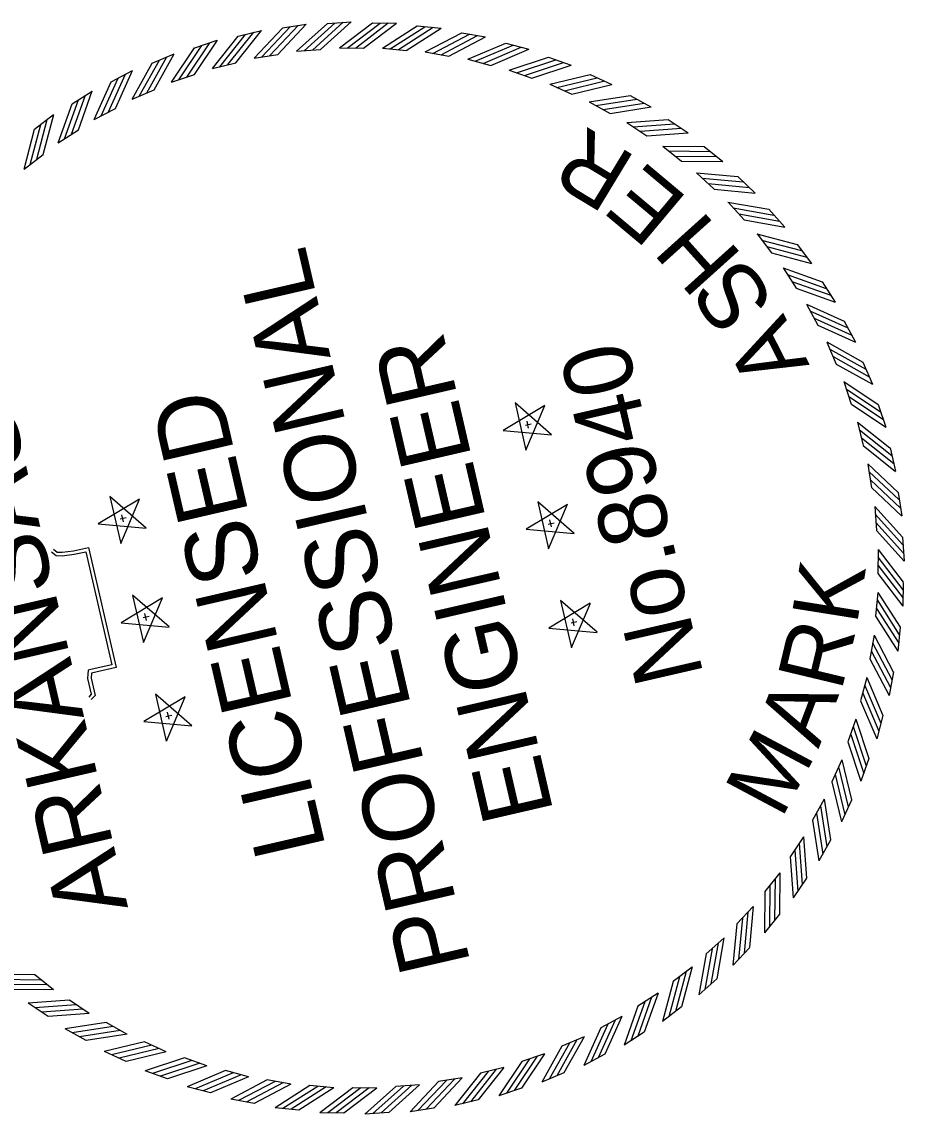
# Model space of a CAD drawing. Extents: x 634644 to 1109508, y 286699 to 700437.
# Drawn here: x 1109100 to 1109183.5, y 700245.2 to 700348.6 of the extents above; entities that cross this region are included whole.
import ezdxf

# ---------------------------------------------------------------- set-up
doc = ezdxf.new("R2010")
doc.units = 0
doc.layers.add('R_Border', color=7, linetype='Continuous')

msp = doc.modelspace()

# ---------------------------------------------------------------- linework, layer by layer
at = {"layer": 'R_Border'}
for p, q in [((1109120.51, 700347.23), (1109122.71, 700347.76)), ((1109124.71, 700348), (1109126.94, 700348.34)), ((1109128.95, 700348.41), (1109131.21, 700348.57)), ((1109133.21, 700348.48), (1109135.48, 700348.45)), ((1109137.47, 700348.19), (1109139.72, 700347.98)), ((1109116.4, 700346.12), (1109118.54, 700346.83)), ((1109141.68, 700347.55), (1109143.91, 700347.15)), ((1109126.04, 700345.79), (1109128.3, 700345.95)), ((1109130.1, 700346.11), (1109132.37, 700346.08)), ((1109134.17, 700346.09), (1109136.43, 700345.87)), ((1109138.22, 700345.73), (1109140.45, 700345.33)), ((1109145.83, 700346.57), (1109148.02, 700345.99)), ((1109112.38, 700344.68), (1109114.47, 700345.56)), ((1109118.07, 700344.17), (1109120.28, 700344.7)), ((1109122.02, 700345.15), (1109124.27, 700345.49)), ((1109142.23, 700345.03), (1109144.42, 700344.45)), ((1109149.89, 700345.24), (1109152.02, 700344.48)), ((1109108.51, 700342.91), (1109110.51, 700343.96)), ((1109114.22, 700342.87), (1109116.37, 700343.58)), ((1109146.17, 700344.01), (1109148.31, 700343.25)), ((1109153.82, 700343.59), (1109155.88, 700342.66)), ((1109150.01, 700342.67), (1109152.08, 700341.74)), ((1109104.79, 700340.82), (1109106.7, 700342.03)), ((1109110.48, 700341.26), (1109112.57, 700342.14)), ((1109157.6, 700341.62), (1109159.57, 700340.52)), ((1109153.73, 700341.02), (1109155.71, 700339.91)), ((1109101.25, 700338.43), (1109103.05, 700339.8)), ((1109106.89, 700339.34), (1109108.9, 700340.39)), ((1109157.3, 700339.06), (1109159.18, 700337.8)), ((1109161.2, 700339.34), (1109163.08, 700338.08)), ((1109103.48, 700337.13), (1109105.39, 700338.35)), ((1109160.69, 700336.82), (1109162.46, 700335.4)), ((1109164.6, 700336.77), (1109166.37, 700335.36)), ((1109100.25, 700334.65), (1109102.06, 700336.02)), ((1109163.89, 700334.3), (1109165.54, 700332.74)), ((1109167.78, 700333.93), (1109169.43, 700332.38)), ((1109166.87, 700331.53), (1109168.38, 700329.84)), ((1109170.72, 700330.84), (1109172.23, 700329.16)), ((1109169.61, 700328.52), (1109170.98, 700326.71)), ((1109173.39, 700327.51), (1109174.76, 700325.71)), ((1109172.09, 700325.29), (1109173.3, 700323.38)), ((1109175.77, 700323.98), (1109176.99, 700322.07)), ((1109174.29, 700321.87), (1109175.35, 700319.87)), ((1109177.86, 700320.26), (1109178.91, 700318.26)), ((1109176.21, 700318.28), (1109177.1, 700316.2)), ((1109179.63, 700316.38), (1109180.52, 700314.3)), ((1109177.82, 700314.55), (1109178.53, 700312.4)), ((1109149.52, 700312.27), (1109145.6, 700309.92)), ((1109146.71, 700312.52), (1109147.73, 700308.07)), ((1109150.15, 700309.52), (1109146.71, 700312.52)), ((1109147.73, 700308.07), (1109149.52, 700312.27)), ((1109181.08, 700312.37), (1109181.79, 700310.22)), ((1109147.69, 700310.41), (1109148.25, 700310.54)), ((1109148, 700310.14), (1109147.85, 700310.8)), ((1109179.12, 700310.69), (1109179.65, 700308.49)), ((1109145.6, 700309.92), (1109150.15, 700309.52)), ((1109182.19, 700308.26), (1109182.72, 700306.06)), ((1109180.1, 700306.74), (1109180.45, 700304.5)), ((1109111.18, 700303.42), (1109107.27, 700301.07)), ((1109108.38, 700303.67), (1109109.4, 700299.22)), ((1109111.82, 700300.68), (1109108.38, 700303.67)), ((1109109.4, 700299.22), (1109111.19, 700303.42)), ((1109182.95, 700304.06), (1109183.3, 700301.83)), ((1109151.67, 700302.92), (1109147.76, 700300.58)), ((1109148.86, 700303.17), (1109149.89, 700298.72)), ((1109152.31, 700300.18), (1109148.86, 700303.17)), ((1109149.89, 700298.72), (1109151.68, 700302.93)), ((1109180.75, 700302.73), (1109180.91, 700300.46)), ((1109109.36, 700301.56), (1109109.92, 700301.69)), ((1109109.67, 700301.29), (1109109.52, 700301.95)), ((1109150.16, 700300.79), (1109150.01, 700301.46)), ((1109107.27, 700301.07), (1109111.82, 700300.67)), ((1109147.76, 700300.57), (1109152.31, 700300.17)), ((1109149.85, 700301.06), (1109150.41, 700301.19)), ((1109183.37, 700299.82), (1109183.53, 700297.56)), ((1109181.06, 700298.67), (1109181.04, 700296.4)), ((1109183.43, 700295.55), (1109183.41, 700293.29)), ((1109113.34, 700294.07), (1109109.43, 700291.73)), ((1109113.98, 700291.33), (1109110.53, 700294.33)), ((1109110.53, 700294.32), (1109111.56, 700289.87)), ((1109111.56, 700289.87), (1109113.35, 700294.08)), ((1109181.04, 700294.6), (1109180.83, 700292.34)), ((1109153.83, 700293.57), (1109149.92, 700291.23)), ((1109154.47, 700290.83), (1109151.02, 700293.83)), ((1109151.02, 700293.82), (1109152.05, 700289.37)), ((1109152.05, 700289.38), (1109153.84, 700293.58)), ((1109111.52, 700292.21), (1109112.08, 700292.34)), ((1109111.83, 700291.94), (1109111.68, 700292.61)), ((1109152.32, 700291.45), (1109152.17, 700292.11)), ((1109109.43, 700291.72), (1109113.98, 700291.32)), ((1109149.92, 700291.23), (1109154.47, 700290.82)), ((1109152.01, 700291.71), (1109152.57, 700291.84)), ((1109183.14, 700291.3), (1109182.93, 700289.05)), ((1109180.68, 700290.55), (1109180.28, 700288.32)), ((1109182.51, 700287.08), (1109182.11, 700284.86)), ((1109179.99, 700286.54), (1109179.41, 700284.35)), ((1109115.5, 700284.73), (1109111.58, 700282.38)), ((1109116.14, 700281.98), (1109112.69, 700284.98)), ((1109112.69, 700284.97), (1109113.71, 700280.52)), ((1109113.72, 700280.53), (1109115.51, 700284.73)), ((1109113.68, 700282.86), (1109114.24, 700282.99)), ((1109113.99, 700282.6), (1109113.84, 700283.26)), ((1109178.97, 700282.6), (1109178.21, 700280.46)), ((1109181.52, 700282.94), (1109180.94, 700280.75)), ((1109111.59, 700282.38), (1109116.14, 700281.97)), ((1109177.63, 700278.76), (1109176.69, 700276.69)), ((1109180.2, 700278.88), (1109179.44, 700276.75)), ((1109175.97, 700275.04), (1109174.87, 700273.06)), ((1109178.54, 700274.95), (1109177.61, 700272.89)), ((1109174.01, 700271.47), (1109172.75, 700269.59)), ((1109176.57, 700271.17), (1109175.47, 700269.2)), ((1109171.77, 700268.08), (1109170.36, 700266.31)), ((1109174.29, 700267.57), (1109173.03, 700265.69)), ((1109169.25, 700264.88), (1109167.7, 700263.23)), ((1109171.73, 700264.16), (1109170.32, 700262.4)), ((1109166.48, 700261.9), (1109164.79, 700260.39)), ((1109168.89, 700260.98), (1109167.34, 700259.34)), ((1109163.47, 700259.16), (1109161.67, 700257.79)), ((1109103.03, 700257), (1109101.26, 700258.41)), ((1109165.79, 700258.05), (1109164.11, 700256.54)), ((1109102.52, 700254.47), (1109100.64, 700255.73)), ((1109106.43, 700254.75), (1109104.54, 700256.02)), ((1109160.25, 700256.68), (1109158.33, 700255.46)), ((1109162.47, 700255.38), (1109160.67, 700254.01)), ((1109109.99, 700252.8), (1109108.01, 700253.9)), ((1109156.83, 700254.47), (1109154.82, 700253.42)), ((1109106.13, 700252.2), (1109104.15, 700253.3)), ((1109158.94, 700252.99), (1109157.03, 700251.78)), ((1109113.71, 700251.14), (1109111.65, 700252.08)), ((1109153.24, 700252.56), (1109151.15, 700251.67)), ((1109109.91, 700250.22), (1109107.85, 700251.16)), ((1109117.55, 700249.8), (1109115.42, 700250.56)), ((1109149.5, 700250.94), (1109147.35, 700250.23)), ((1109155.22, 700250.91), (1109153.21, 700249.85)), ((1109145.65, 700249.64), (1109143.44, 700249.11)), ((1109113.84, 700248.57), (1109111.71, 700249.33)), ((1109121.49, 700248.78), (1109119.3, 700249.36)), ((1109141.7, 700248.67), (1109139.46, 700248.32)), ((1109151.34, 700249.14), (1109149.26, 700248.25)), ((1109117.89, 700247.25), (1109115.7, 700247.83)), ((1109125.5, 700248.09), (1109123.27, 700248.49)), ((1109129.55, 700247.73), (1109127.3, 700247.94)), ((1109133.62, 700247.71), (1109131.36, 700247.73)), ((1109137.68, 700248.02), (1109135.42, 700247.86)), ((1109147.33, 700247.69), (1109145.18, 700246.98)), ((1109122.04, 700246.26), (1109119.81, 700246.66)), ((1109143.21, 700246.58), (1109141.01, 700246.05)), ((1109126.25, 700245.62), (1109124, 700245.84)), ((1109134.77, 700245.4), (1109132.52, 700245.24)), ((1109139.01, 700245.82), (1109136.78, 700245.47)), ((1109130.51, 700245.34), (1109128.25, 700245.36))]:
    msp.add_line(p, q, dxfattribs=at)
for points in [[(1109120.28, 700344.7), (1109122.71, 700347.76)], [(1109122.02, 700345.14), (1109124.7, 700347.99)], [(1109122.74, 700345.25), (1109125.43, 700348.1)], [(1109123.52, 700345.39), (1109126.2, 700348.24)], [(1109124.26, 700345.49), (1109126.94, 700348.34)], [(1109126.04, 700345.79), (1109128.95, 700348.41)], [(1109126.77, 700345.84), (1109129.67, 700348.46)], [(1109127.55, 700345.91), (1109130.46, 700348.53)], [(1109128.3, 700345.96), (1109131.21, 700348.58)], [(1109130.1, 700346.11), (1109133.21, 700348.48)], [(1109130.82, 700346.09), (1109133.94, 700348.46)], [(1109131.61, 700346.1), (1109134.72, 700348.47)], [(1109132.36, 700346.08), (1109135.48, 700348.45)], [(1109134.17, 700346.08), (1109137.46, 700348.19)], [(1109134.89, 700346.01), (1109138.19, 700348.11)], [(1109135.67, 700345.95), (1109138.97, 700348.06)], [(1109136.42, 700345.87), (1109139.72, 700347.98)], [(1109116.37, 700343.58), (1109118.55, 700346.83)], [(1109118.07, 700344.17), (1109120.51, 700347.23)], [(1109118.78, 700344.33), (1109121.22, 700347.39)], [(1109119.54, 700344.53), (1109121.98, 700347.59)], [(1109138.22, 700345.73), (1109141.68, 700347.55)], [(1109138.93, 700345.59), (1109142.4, 700347.42)], [(1109139.71, 700345.47), (1109143.17, 700347.29)], [(1109140.45, 700345.33), (1109143.91, 700347.15)], [(1109114.22, 700342.87), (1109116.39, 700346.12)], [(1109114.91, 700343.09), (1109117.09, 700346.34)], [(1109115.65, 700343.35), (1109117.83, 700346.6)], [(1109142.23, 700345.03), (1109145.83, 700346.57)], [(1109142.93, 700344.84), (1109146.53, 700346.37)], [(1109143.69, 700344.65), (1109147.29, 700346.19)], [(1109144.42, 700344.45), (1109148.02, 700345.99)], [(1109110.48, 700341.25), (1109112.38, 700344.67)], [(1109111.15, 700341.53), (1109113.06, 700344.95)], [(1109111.87, 700341.85), (1109113.77, 700345.28)], [(1109112.57, 700342.14), (1109114.47, 700345.56)], [(1109146.17, 700344.01), (1109149.88, 700345.24)], [(1109146.85, 700343.76), (1109150.57, 700344.99)], [(1109147.6, 700343.51), (1109151.31, 700344.74)], [(1109108.23, 700340.05), (1109109.84, 700343.62)], [(1109108.9, 700340.39), (1109110.51, 700343.96)], [(1109148.3, 700343.25), (1109152.02, 700344.49)], [(1109150.01, 700342.67), (1109153.81, 700343.59)], [(1109106.89, 700339.34), (1109108.5, 700342.9)], [(1109107.54, 700339.67), (1109109.15, 700343.24)], [(1109150.67, 700342.36), (1109154.47, 700343.28)], [(1109151.39, 700342.06), (1109155.2, 700342.98)], [(1109152.07, 700341.74), (1109155.88, 700342.66)], [(1109104.75, 700337.95), (1109106.06, 700341.64)], [(1109105.39, 700338.35), (1109106.7, 700342.04)], [(1109153.73, 700341.02), (1109157.59, 700341.62)], [(1109103.47, 700337.13), (1109104.79, 700340.82)], [(1109104.09, 700337.51), (1109105.4, 700341.2)], [(1109154.36, 700340.66), (1109158.23, 700341.26)], [(1109155.05, 700340.29), (1109158.92, 700340.89)], [(1109155.71, 700339.92), (1109159.58, 700340.52)], [(1109102.05, 700336.02), (1109103.06, 700339.81)], [(1109100.25, 700334.65), (1109101.25, 700338.43)], [(1109100.83, 700335.08), (1109101.84, 700338.87)], [(1109101.45, 700335.57), (1109102.45, 700339.35)], [(1109157.29, 700339.06), (1109161.2, 700339.34)], [(1109157.89, 700338.65), (1109161.8, 700338.93)], [(1109158.56, 700338.23), (1109162.46, 700338.51)], [(1109159.18, 700337.8), (1109163.08, 700338.08)], [(1109160.69, 700336.82), (1109164.6, 700336.77)], [(1109161.25, 700336.36), (1109165.17, 700336.31)], [(1109161.88, 700335.88), (1109165.79, 700335.84)], [(1109162.46, 700335.4), (1109166.38, 700335.36)], [(1109163.88, 700334.3), (1109167.78, 700333.93)], [(1109164.41, 700333.79), (1109168.31, 700333.43)], [(1109164.99, 700333.27), (1109168.89, 700332.9)], [(1109165.54, 700332.75), (1109169.43, 700332.38)], [(1109166.86, 700331.53), (1109170.72, 700330.84)], [(1109167.34, 700330.98), (1109171.2, 700330.29)], [(1109167.88, 700330.41), (1109171.74, 700329.72)], [(1109168.38, 700329.84), (1109172.23, 700329.16)], [(1109169.6, 700328.52), (1109173.39, 700327.52)], [(1109170.04, 700327.93), (1109173.82, 700326.93)], [(1109170.53, 700327.32), (1109174.31, 700326.32)], [(1109170.98, 700326.71), (1109174.76, 700325.71)], [(1109172.08, 700325.29), (1109175.77, 700323.98)], [(1109172.47, 700324.68), (1109176.16, 700323.36)], [(1109172.91, 700324.02), (1109176.59, 700322.71)], [(1109173.3, 700323.38), (1109176.99, 700322.07)], [(1109174.29, 700321.88), (1109177.86, 700320.26)], [(1109174.62, 700321.23), (1109178.19, 700319.62)], [(1109175, 700320.54), (1109178.57, 700318.93)], [(1109175.35, 700319.87), (1109178.92, 700318.26)], [(1109176.21, 700318.29), (1109179.63, 700316.39)], [(1109176.49, 700317.61), (1109179.91, 700315.71)], [(1109176.81, 700316.9), (1109180.23, 700315)], [(1109177.1, 700316.2), (1109180.52, 700314.3)], [(1109177.82, 700314.55), (1109181.07, 700312.37)], [(1109178.04, 700313.86), (1109181.3, 700311.68)], [(1109178.31, 700313.12), (1109181.56, 700310.94)], [(1109178.54, 700312.4), (1109181.79, 700310.22)], [(1109179.12, 700310.7), (1109182.18, 700308.26)], [(1109179.29, 700309.99), (1109182.35, 700307.55)], [(1109179.49, 700309.23), (1109182.55, 700306.79)], [(1109179.66, 700308.49), (1109182.72, 700306.05)], [(1109180.1, 700306.75), (1109182.95, 700304.06)], [(1109180.2, 700306.03), (1109183.05, 700303.34)], [(1109180.34, 700305.25), (1109183.19, 700302.57)], [(1109180.45, 700304.51), (1109183.3, 700301.82)], [(1109180.75, 700302.73), (1109183.37, 700299.82)], [(1109180.79, 700302), (1109183.41, 700299.09)], [(1109180.86, 700301.22), (1109183.48, 700298.31)], [(1109180.91, 700300.47), (1109183.53, 700297.56)], [(1109102.84, 700298.44), (1109103.28, 700298.09), (1109103.86, 700298.07), (1109104.99, 700298.2), (1109106.09, 700298.45), (1109108.56, 700287.75), (1109106.99, 700287.39), (1109106.33, 700287.23), (1109106.27, 700286.45), (1109106.61, 700284.96), (1109106.37, 700284.7)], [(1109103.04, 700298.7), (1109103.4, 700298.41), (1109103.85, 700298.4), (1109104.93, 700298.53), (1109106.34, 700298.85), (1109108.96, 700287.5), (1109107.06, 700287.06), (1109106.64, 700286.97), (1109106.6, 700286.47), (1109106.98, 700284.86), (1109106.61, 700284.47)], [(1109181.06, 700298.67), (1109183.43, 700295.56)], [(1109181.04, 700297.94), (1109183.41, 700294.83)], [(1109181.05, 700297.16), (1109183.42, 700294.04)], [(1109181.04, 700296.4), (1109183.41, 700293.29)], [(1109181.04, 700294.6), (1109183.14, 700291.3)], [(1109180.91, 700293.09), (1109183.01, 700289.8)], [(1109180.96, 700293.88), (1109183.07, 700290.58)], [(1109180.83, 700292.35), (1109182.93, 700289.05)], [(1109180.54, 700289.83), (1109182.37, 700286.37)], [(1109180.68, 700290.55), (1109182.5, 700287.09)], [(1109180.42, 700289.06), (1109182.25, 700285.6)], [(1109180.28, 700288.32), (1109182.11, 700284.86)], [(1109179.79, 700285.84), (1109181.33, 700282.24)], [(1109179.99, 700286.54), (1109181.52, 700282.94)], [(1109179.61, 700285.07), (1109181.14, 700281.47)], [(1109179.41, 700284.35), (1109180.94, 700280.75)], [(1109178.97, 700282.6), (1109180.2, 700278.89)], [(1109178.72, 700281.92), (1109179.95, 700278.2)], [(1109178.47, 700281.17), (1109179.7, 700277.46)], [(1109178.21, 700280.46), (1109179.44, 700276.75)], [(1109177.63, 700278.76), (1109178.54, 700274.96)], [(1109177.32, 700278.1), (1109178.24, 700274.3)], [(1109176.69, 700276.69), (1109177.61, 700272.89)], [(1109177.01, 700277.38), (1109177.93, 700273.57)], [(1109175.61, 700274.41), (1109176.21, 700270.54)], [(1109175.97, 700275.04), (1109176.57, 700271.18)], [(1109175.24, 700273.72), (1109175.85, 700269.85)], [(1109174.87, 700273.06), (1109175.47, 700269.19)], [(1109174.01, 700271.48), (1109174.29, 700267.57)], [(1109173.18, 700270.21), (1109173.46, 700266.31)], [(1109173.6, 700270.87), (1109173.88, 700266.97)], [(1109172.75, 700269.59), (1109173.04, 700265.69)], [(1109171.31, 700267.52), (1109171.27, 700263.6)], [(1109171.77, 700268.08), (1109171.73, 700264.17)], [(1109170.36, 700266.31), (1109170.32, 700262.39)], [(1109170.83, 700266.89), (1109170.79, 700262.98)], [(1109168.75, 700264.36), (1109168.38, 700260.46)], [(1109169.25, 700264.88), (1109168.89, 700260.99)], [(1109167.7, 700263.23), (1109167.33, 700259.34)], [(1109168.22, 700263.78), (1109167.86, 700259.88)], [(1109165.94, 700261.42), (1109165.25, 700257.57)], [(1109166.48, 700261.91), (1109165.79, 700258.05)], [(1109164.8, 700260.39), (1109164.11, 700256.53)], [(1109165.36, 700260.89), (1109164.68, 700257.03)], [(1109163.47, 700259.17), (1109162.47, 700255.38)], [(1109101.26, 700258.41), (1109097.35, 700258.45)], [(1109101.85, 700257.93), (1109097.93, 700257.98)], [(1109161.67, 700257.79), (1109160.67, 700254.01)], [(1109162.27, 700258.24), (1109161.27, 700254.46)], [(1109162.89, 700258.73), (1109161.89, 700254.95)], [(1109102.47, 700257.46), (1109098.56, 700257.5)], [(1109103.04, 700257), (1109099.12, 700257.04)], [(1109104.54, 700256.01), (1109100.64, 700255.73)], [(1109158.98, 700255.86), (1109157.67, 700252.18)], [(1109159.63, 700256.3), (1109158.32, 700252.61)], [(1109160.25, 700256.68), (1109158.94, 700253)], [(1109105.17, 700255.59), (1109101.26, 700255.31)], [(1109105.83, 700255.16), (1109101.92, 700254.88)], [(1109106.43, 700254.75), (1109102.53, 700254.47)], [(1109158.34, 700255.46), (1109157.03, 700251.78)], [(1109108.01, 700253.9), (1109104.15, 700253.3)], [(1109155.49, 700253.76), (1109153.88, 700250.2)], [(1109156.18, 700254.14), (1109154.57, 700250.58)], [(1109156.83, 700254.48), (1109155.22, 700250.91)], [(1109108.67, 700253.52), (1109104.8, 700252.92)], [(1109109.36, 700253.16), (1109105.5, 700252.56)], [(1109110, 700252.8), (1109106.13, 700252.2)], [(1109154.82, 700253.42), (1109153.21, 700249.85)], [(1109111.65, 700252.07), (1109107.84, 700251.16)], [(1109112.33, 700251.76), (1109108.53, 700250.84)], [(1109151.15, 700251.67), (1109149.25, 700248.25)], [(1109151.85, 700251.96), (1109149.95, 700248.54)], [(1109152.57, 700252.28), (1109150.67, 700248.86)], [(1109153.24, 700252.56), (1109151.34, 700249.14)], [(1109113.05, 700251.45), (1109109.25, 700250.53)], [(1109113.71, 700251.14), (1109109.91, 700250.22)], [(1109115.42, 700250.56), (1109111.7, 700249.33)], [(1109148.81, 700250.73), (1109146.64, 700247.47)], [(1109149.51, 700250.95), (1109147.33, 700247.69)], [(1109116.13, 700250.3), (1109112.41, 700249.07)], [(1109116.87, 700250.05), (1109113.16, 700248.82)], [(1109117.56, 700249.8), (1109113.84, 700248.57)], [(1109145.65, 700249.65), (1109143.21, 700246.58)], [(1109147.35, 700250.23), (1109145.18, 700246.98)], [(1109148.07, 700250.46), (1109145.89, 700247.21)], [(1109119.3, 700249.36), (1109115.7, 700247.83)], [(1109120.03, 700249.16), (1109116.43, 700247.63)], [(1109120.79, 700248.97), (1109117.19, 700247.44)], [(1109121.49, 700248.78), (1109117.89, 700247.25)], [(1109140.98, 700248.56), (1109138.3, 700245.71)], [(1109141.7, 700248.67), (1109139.02, 700245.82)], [(1109143.45, 700249.11), (1109141.01, 700246.05)], [(1109144.18, 700249.28), (1109141.74, 700246.22)], [(1109144.94, 700249.48), (1109142.5, 700246.42)], [(1109123.27, 700248.48), (1109119.81, 700246.66)], [(1109124.01, 700248.34), (1109120.55, 700246.52)], [(1109124.79, 700248.22), (1109121.33, 700246.4)], [(1109125.5, 700248.09), (1109122.04, 700246.26)], [(1109127.3, 700247.94), (1109124, 700245.84)], [(1109128.05, 700247.86), (1109124.75, 700245.76)], [(1109128.83, 700247.81), (1109125.53, 700245.7)], [(1109129.56, 700247.73), (1109126.26, 700245.63)], [(1109131.36, 700247.73), (1109128.24, 700245.36)], [(1109132.11, 700247.72), (1109129, 700245.35)], [(1109132.9, 700247.72), (1109129.78, 700245.35)], [(1109133.63, 700247.71), (1109130.51, 700245.34)], [(1109135.42, 700247.86), (1109132.51, 700245.24)], [(1109136.17, 700247.9), (1109133.27, 700245.29)], [(1109136.96, 700247.98), (1109134.05, 700245.36)], [(1109137.68, 700248.02), (1109134.77, 700245.4)], [(1109139.46, 700248.32), (1109136.78, 700245.47)], [(1109140.21, 700248.43), (1109137.52, 700245.58)]]:
    msp.add_lwpolyline(points, dxfattribs=at)

# ---------------------------------------------------------------- texts
for s, height, rotation, p in [('R', 6.25, 148.7825, (1109158.34, 700335.71)), ('E', 6.25, 140.0272, (1109163.22, 700331.8)), ('H', 6.25, 132.0016, (1109168.35, 700326.41)), ('PROFESSIONAL', 6.7161, 103, (1109142.52, 700259.47)), ('S', 6.25, 124.7056, (1109171.43, 700322.02)), ('A', 6.25, 117.0448, (1109174.6, 700316.12)), ('ENGINEER', 6.716, 103, (1109150.38, 700273.76)), ('No.8940', 6.476, 103, (1109164.57, 700286.76)), ('LICENSED', 6.716, 103, (1109128.83, 700270.43)), ('ARKANSAS', 6.716, 103, (1109110.1, 700264.79)), ('K', 6.25, 80.9296, (1109179.05, 700291.43)), ('R', 6.25, 76.552, (1109177.58, 700285.14)), ('A', 6.25, 69.256, (1109175.42, 700279.75)), ('M', 6.25, 61.9599, (1109171.9, 700273.08))]:
    msp.add_text(s, height=height, rotation=rotation, dxfattribs=at).set_placement(p)

doc.saveas('drawing.dxf')
